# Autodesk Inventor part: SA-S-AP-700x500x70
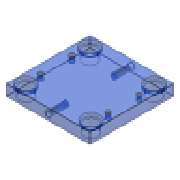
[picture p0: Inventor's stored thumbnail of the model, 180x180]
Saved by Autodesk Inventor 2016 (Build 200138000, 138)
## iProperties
Created: 2015-02
Part Number: SA-S-AP-700x500x70
Material: S 55 C
Description: Cavity Plate
Document SubType Name: Modeling
Designer: Sandeep
Standard Revision: 1
Manufacturer: FUTABA
Language: en-US
Size Designation: 700x500x70
Categories: <MemberInstance><Categories><Category DisplayName="Mold" InternalName="349578f2-f4d4-4954-8c09-8e99297a61c0" Mnemonic="MOLD"><Category DisplayName="Mold Plates"
Density: 7.85 g/cm^3
Appearance: Clear - Blue
IsCustomPart: 1
Author: Sandeep
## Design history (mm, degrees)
sketch "Sketch1"
  geometry: L1 (-250, 350)-(250, 350); L2 (250, 350)-(250, -350); L3 (250, -350)-(-250, -350); L4 (-250, -350)-(-250, 350); 3 further points
  constraints: 8 end point, 2 midpoint, 2 parallel, 1 horizontal, 1 horizontal alignment, 1 perpendicular, 1 vertical alignment
  dimensions: "d123" = 500 distance between parallel lines of L2 L4 (= W_); "d124" = 700 distance between parallel lines of L3 L1 (= L)
extrude "Extrusion1" new body sketch "Sketch1" distance "d20" = 70 (= H_); taper "d30" = 0 deg
sketch "Sketch2"
  geometry: 4 further points
  constraints: 1 horizontal alignment
  dimensions: "d125" = 205 horizontal distance of point (0, 0) point (-205, 243) (= 0.5 x S1_W); "d126" = 243 vertical distance of point (0, 0) point (-205, 243) (= 0.5 x S1_L); "d127" = 207 horizontal distance of point (0, 0) point (-207, 307) (= 0.5 x GB_W); "d128" = 307 vertical distance of point (0, 0) point (-207, 307) (= 0.5 x GB_L); "d129" = 207 horizontal distance of point (0, 0) point (207, 307) (= 0.5 x GB_W)
feature "Sculpt1"
feature "Sculpt2"
feature "Sculpt6"
body "Solid1"
sketch "Sketch3"
  geometry: L1 (500, 0)-(0, 0) reference; 3 further points
  constraints: 1 midpoint, 1 vertical alignment
  dimensions: "d169" = 35 distance from line of L1 point (250, 35) (= 0.5 x H_)
hole "Hole1" sketch "Sketch3" diameter "d170" = 31.67; stored, may be unused: countersink angle "d174" = 90 deg, drill point angle "d176" = 118 deg; dims "d171" = 59 (= le), "d172" = 4, "d173" = 2, "d175" = 82 (= ke)
sketch "Sketch4"
  geometry: L1 (0, 0)-(500, 0) reference; 4 further points
  constraints: 2 midpoint, 2 vertical alignment
  dimensions: "d177" = 35 distance from line of L1 point (250, -35) (= 0.5 x H_)
hole "Hole2" sketch "Sketch4" diameter "d178" = 31.67; stored, may be unused: countersink angle "d182" = 90 deg, drill point angle "d184" = 118 deg; dims "d179" = 59 (= le), "d180" = 4, "d181" = 2, "d183" = 82 (= ke)
hole "Hole3" sketch "Sketch2" diameter "d130" = 55 (= GB_d1); stored, may be unused: countersink angle "d134" = 90 deg, drill point angle "d136" = 0 deg; dims "d131" = 6, "d132" = 62 (= GB_d2), "d133" = 10 (= GB_k), "d135" = 70 (= H_)
pattern_linear "Rectangular Pattern1" dims "d159" = 614 (computed from GB_L, Nl)
hole "Hole4" sketch "Sketch2" diameter "d137" = 55 (= GB_d1); stored, may be unused: countersink angle "d141" = 90 deg, drill point angle "d143" = 0 deg; dims "d138" = 6, "d139" = 62 (= GB_d2), "d140" = 10 (= GB_k), "d142" = 70 (= H_)
pattern_linear "Rectangular Pattern2" dims "d162" = 612 (computed from GB_L2, GB_L1, Nl)
hole "Hole5" sketch "Sketch2" diameter "d144" = 13.835; stored, may be unused: countersink angle "d148" = 90 deg, drill point angle "d150" = 118 deg; dims "d145" = 20 (= H_l), "d146" = 62 (= GB_d2), "d147" = 10 (= GB_k), "d149" = 30 (= H_u)
pattern_linear "Rectangular Pattern3" dims "d153" = 243 (computed from S1_L, Ns)
chamfer "Chamfer1" distance "d185" = 0.5; stored, may be unused: second distance "d186" = 2, angle "d187" = 45 deg
feature "Surface1"
body "Srf1"
feature "Surface2"
body "Srf2"
feature "Surface6"
body "Srf6"
other parameters: "L" = 700 [user parameter; used in 1 equation term], "W_" = 500 [user parameter; used in 1 equation term], "H_" = 70 [user parameter; used in 5 equation terms], "GB_W" = 414 [user parameter; used in 2 equation terms], "GB_d1" = 55 [user parameter; used in 2 equation terms], "GB_d2" = 62 [user parameter; used in 3 equation terms], "GB_k" = 10 [user parameter; used in 3 equation terms], "S1_L" = 486 [user parameter; used in 2 equation terms], "GB_L1" = 307 [user parameter; used in 1 equation term], "GB_L2" = 305 [user parameter; used in 1 equation term], "GB_L" = 614 [user parameter; used in 2 equation terms], "le" = 59 [user parameter; used in 2 equation terms], "ke" = 82 [user parameter; used in 2 equation terms], "H_l" = 20 [user parameter; used in 1 equation term], "H_u" = 30 [user parameter; used in 1 equation term]
